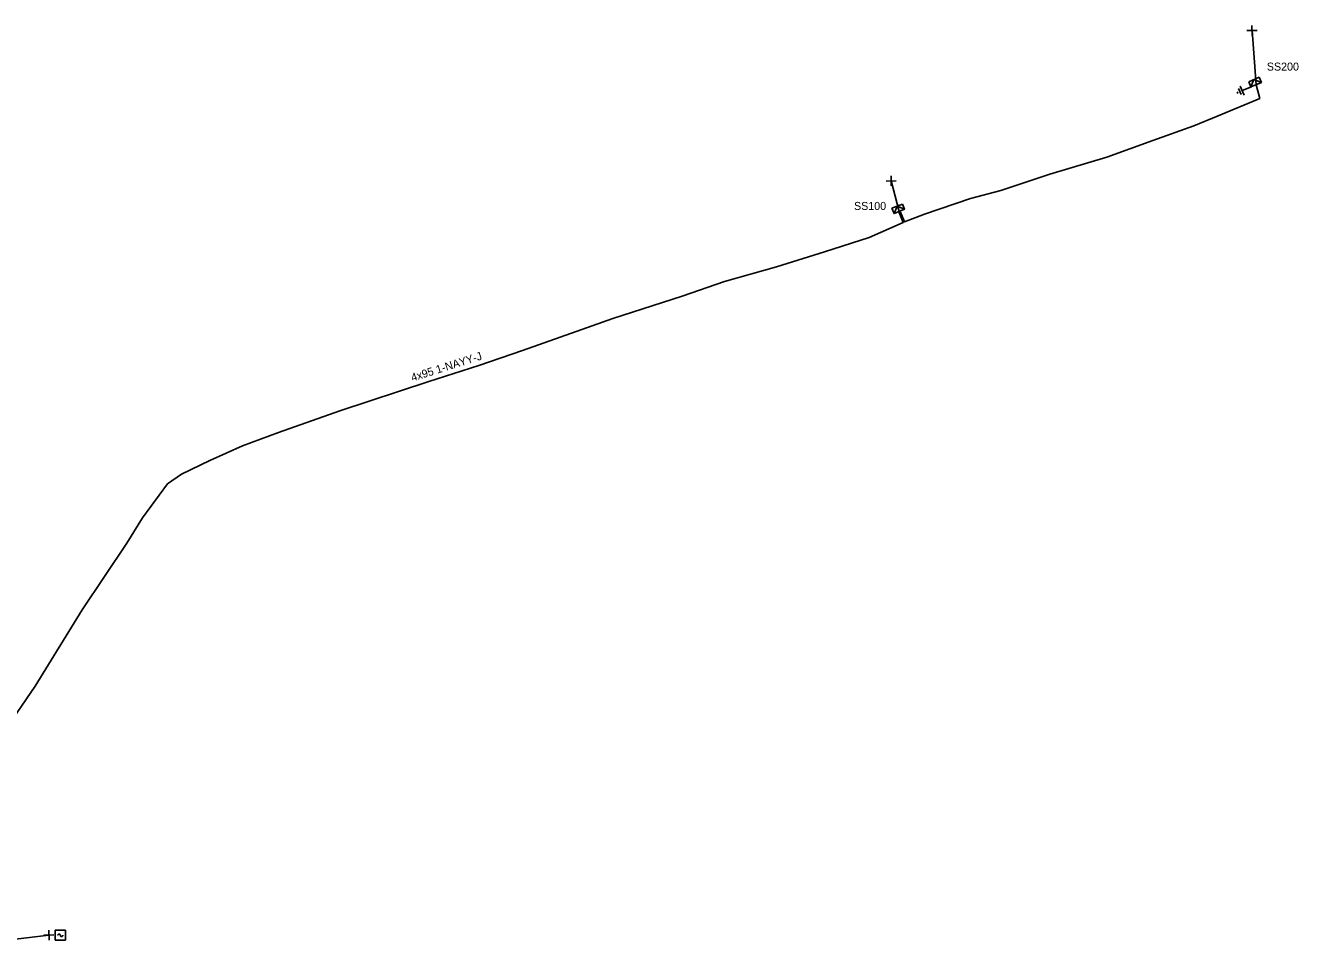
# Model space of a CAD drawing. Extents: x -762284 to -761419, y -1155250 to -1154991.
# Drawn here: x -761576.8 to -761418.6, y -1155129.8 to -1155015.6 of the extents above; entities that cross this region are included whole.
import ezdxf

# ---------------------------------------------------------------- set-up
doc = ezdxf.new("R2010")
doc.units = 0
for name, color, linetype in [('Vrstva 15', 7, 'Continuous'), ('Vrstva 31', 7, 'Continuous'), ('Vrstva 33', 7, 'Continuous'), ('Vrstva 34', 7, 'Continuous'), ('Vrstva 5', 7, 'Continuous'), ('Vrstva 59', 7, 'Continuous'), ('Vrstva 6', 7, 'Continuous')]:
    doc.layers.add(name, color=color, linetype=linetype)

msp = doc.modelspace()

# ---------------------------------------------------------------- linework, layer by layer
at = {"layer": 'Vrstva 15'}
for points in [[(-761425.764, -1155024.147), (-761426.071, -1155023.422)], [(-761425.384, -1155024.248), (-761425.873, -1155023.097)], [(-761424.478, -1155023.184), (-761425.628, -1155023.672)], [(-761426.204, -1155023.917), (-761426.254, -1155023.799)], [(-761426.152, -1155024.039), (-761426.204, -1155023.917)]]:
    msp.add_lwpolyline(points, dxfattribs=at)
at = {"layer": 'Vrstva 31'}
for points in [[(-761423.517, -1155022.011), (-761424.806, -1155022.558)], [(-761423.517, -1155022.011), (-761423.243, -1155022.655), (-761424.532, -1155023.202), (-761424.806, -1155022.558)], [(-761424.161, -1155022.285), (-761424.532, -1155023.202)], [(-761424.161, -1155022.285), (-761423.243, -1155022.655)], [(-761467.85, -1155037.767), (-761469.148, -1155038.291)], [(-761467.85, -1155037.767), (-761467.588, -1155038.416), (-761468.886, -1155038.94), (-761469.148, -1155038.291)], [(-761468.499, -1155038.029), (-761468.886, -1155038.94)], [(-761468.499, -1155038.029), (-761467.588, -1155038.416)]]:
    msp.add_lwpolyline(points, dxfattribs=at)
at = {"layer": 'Vrstva 34'}
for points in [[(-761424.389, -1155016.825), (-761424.411, -1155015.575)], [(-761425.025, -1155016.211), (-761423.775, -1155016.189)], [(-761469.239, -1155035.515), (-761469.261, -1155034.265)], [(-761469.875, -1155034.901), (-761468.625, -1155034.879)], [(-761573.899, -1155129.195), (-761573.921, -1155127.945)], [(-761571.865, -1155127.976), (-761573.115, -1155127.976)], [(-761573.115, -1155127.976), (-761573.115, -1155129.226)], [(-761571.865, -1155129.226), (-761571.865, -1155127.976)], [(-761574.535, -1155128.581), (-761573.285, -1155128.559)], [(-761573.115, -1155129.226), (-761571.865, -1155129.226)], [(-761572.49, -1155128.601), (-761572.491, -1155128.585), (-761572.494, -1155128.569), (-761572.498, -1155128.554), (-761572.503, -1155128.539), (-761572.511, -1155128.525), (-761572.519, -1155128.511), (-761572.529, -1155128.499), (-761572.54, -1155128.487), (-761572.553, -1155128.477), (-761572.566, -1155128.469), (-761572.58, -1155128.461), (-761572.595, -1155128.455), (-761572.611, -1155128.451), (-761572.626, -1155128.449), (-761572.642, -1155128.448), (-761572.658, -1155128.449), (-761572.674, -1155128.451), (-761572.69, -1155128.455), (-761572.704, -1155128.461), (-761572.719, -1155128.468), (-761572.732, -1155128.476), (-761572.745, -1155128.487), (-761572.756, -1155128.498), (-761572.766, -1155128.51), (-761572.775, -1155128.523), (-761572.782, -1155128.538), (-761572.788, -1155128.552), (-761572.792, -1155128.568), (-761572.795, -1155128.584), (-761572.796, -1155128.6), (-761572.796, -1155128.601)], [(-761572.491, -1155128.601), (-761572.49, -1155128.617), (-761572.488, -1155128.632), (-761572.484, -1155128.648), (-761572.479, -1155128.662), (-761572.472, -1155128.677), (-761572.464, -1155128.69), (-761572.454, -1155128.702), (-761572.443, -1155128.714), (-761572.431, -1155128.724), (-761572.418, -1155128.733), (-761572.404, -1155128.74), (-761572.39, -1155128.746), (-761572.374, -1155128.75), (-761572.359, -1155128.753), (-761572.343, -1155128.754), (-761572.328, -1155128.754), (-761572.312, -1155128.751), (-761572.297, -1155128.748), (-761572.282, -1155128.742), (-761572.268, -1155128.735), (-761572.254, -1155128.727), (-761572.242, -1155128.718), (-761572.231, -1155128.707), (-761572.221, -1155128.695), (-761572.212, -1155128.682), (-761572.204, -1155128.668), (-761572.198, -1155128.653), (-761572.194, -1155128.638), (-761572.191, -1155128.623), (-761572.19, -1155128.607), (-761572.19, -1155128.606)]]:
    msp.add_lwpolyline(points, dxfattribs=at)
at = {"layer": 'Vrstva 5'}
msp.add_lwpolyline([(-761579.55, -1155103.39), (-761575.64, -1155097.65), (-761569.77, -1155088.19), (-761564.24, -1155079.89), (-761562.3, -1155076.76), (-761559.18, -1155072.52), (-761557.42, -1155071.33), (-761553.9, -1155069.61), (-761549.84, -1155067.8), (-761545.38, -1155066.13), (-761537.77, -1155063.46), (-761526.71, -1155059.79), (-761520.47, -1155057.81), (-761515.06, -1155055.97), (-761507.67, -1155053.35), (-761503.84, -1155051.99), (-761495.22, -1155049.19), (-761489.97, -1155047.4), (-761483.5, -1155045.58), (-761477.52, -1155043.71), (-761471.99, -1155041.91), (-761467.74, -1155040.05), (-761468.27, -1155038.81), (-761468.24, -1155038.68), (-761468.09, -1155038.78), (-761467.58, -1155039.98), (-761465.1, -1155039.02), (-761459.4, -1155037.09), (-761455.6, -1155036.09), (-761449.54, -1155034.06), (-761442.44, -1155031.93), (-761436.71, -1155029.85), (-761431.62, -1155028.06), (-761428.6, -1155026.79), (-761423.44, -1155024.65), (-761423.89, -1155022.93)], dxfattribs=at)
at = {"layer": 'Vrstva 59'}
for points in [[(-761423.89, -1155022.93), (-761424.4, -1155016.2)], [(-761468.24, -1155038.68), (-761469.25, -1155034.89)], [(-761583.63, -1155129.75), (-761573.91, -1155128.57)]]:
    msp.add_lwpolyline(points, dxfattribs=at)

# ---------------------------------------------------------------- texts
at = {"layer": 'Vrstva 33'}
for s, p in [('SS200', (-761422.56, -1155021.18)), ('SS100', (-761473.86, -1155038.49))]:
    msp.add_text(s, height=0.9943, dxfattribs=at).set_placement(p)
at = {"layer": 'Vrstva 6'}
msp.add_text('4x95 1-NAYY-J', height=0.99429, rotation=17.60463, dxfattribs=at).set_placement((-761528.74, -1155059.82))

doc.saveas('drawing.dxf')
